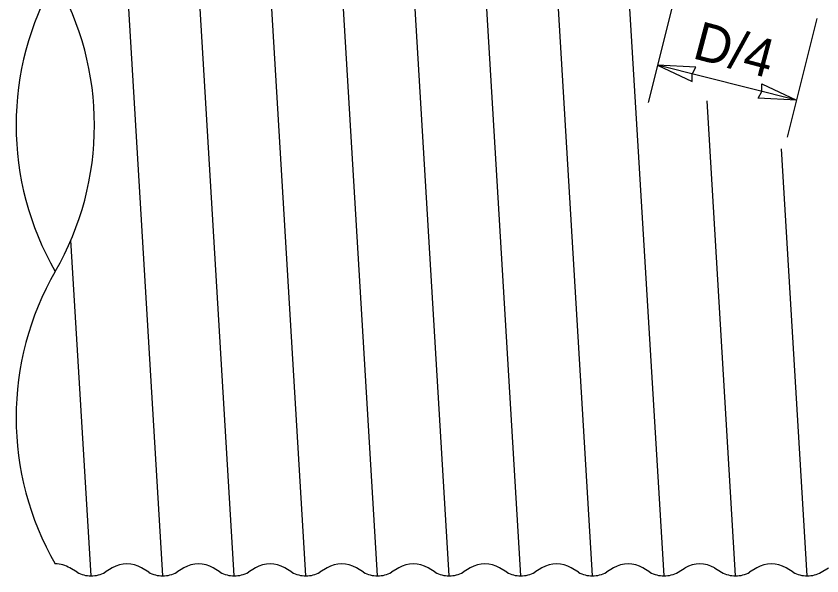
# Model space of a CAD drawing. Extents: x 99862 to 103151, y 100000 to 102076.
# Drawn here: x 100599.7 to 100937.3, y 101551.1 to 101785.5 of the extents above; entities that cross this region are included whole.
import ezdxf

# ---------------------------------------------------------------- set-up
doc = ezdxf.new("R2010")
doc.units = 0
for name, color, linetype in [('Level 1', 7, 'Continuous'), ('Level 15', 7, 'Continuous'), ('Level 20', 7, 'Continuous')]:
    doc.layers.add(name, color=color, linetype=linetype)

msp = doc.modelspace()

# ---------------------------------------------------------------- linework, layer by layer
at = {"layer": 'Level 1'}
for p, q in [((100661.12, 101551.13), (100646.12, 101801.13)), ((100691.12, 101551.13), (100676.12, 101801.13)), ((100721.12, 101551.13), (100706.12, 101801.13)), ((100751.12, 101551.13), (100736.12, 101801.13)), ((100781.12, 101551.13), (100766.12, 101801.13)), ((100811.12, 101551.13), (100796.12, 101801.13)), ((100841.12, 101551.13), (100826.12, 101801.13)), ((100871.12, 101551.13), (100856.12, 101801.13)), ((100901.12, 101551.13), (100889.19, 101750.04)), ((100931.12, 101551.13), (100920.39, 101729.9)), ((100631.12, 101551.13), (100622.68, 101691.75)), ((100625.25, 101552.66), (100622.26, 101554.44)), ((100622.26, 101554.44), (100622.26, 101554.44)), ((100639.98, 101554.44), (100637, 101552.66)), ((100655.25, 101552.66), (100652.26, 101554.44)), ((100669.98, 101554.44), (100667, 101552.66)), ((100685.25, 101552.66), (100682.26, 101554.44)), ((100699.98, 101554.44), (100697, 101552.66)), ((100715.25, 101552.66), (100712.26, 101554.44)), ((100729.98, 101554.44), (100727, 101552.66)), ((100745.25, 101552.66), (100742.26, 101554.44)), ((100759.98, 101554.44), (100757, 101552.66)), ((100775.25, 101552.66), (100772.26, 101554.44)), ((100789.98, 101554.44), (100787, 101552.66)), ((100805.25, 101552.66), (100802.26, 101554.44)), ((100819.98, 101554.44), (100817, 101552.66)), ((100835.25, 101552.66), (100832.26, 101554.44)), ((100849.98, 101554.44), (100847, 101552.66)), ((100865.25, 101552.66), (100862.26, 101554.44)), ((100877, 101552.66), (100879.98, 101554.44)), ((100892.26, 101554.44), (100895.25, 101552.66)), ((100909.98, 101554.44), (100907, 101552.66)), ((100925.25, 101552.66), (100922.26, 101554.44)), ((100937, 101552.66), (100939.98, 101554.44))]:
    msp.add_line(p, q, dxfattribs=at)
msp.add_lwpolyline([(100926.64, 101750.39), (100910.63, 101751.21), (100912.09, 101754.02), (100912.13, 101757.19)], close=True, dxfattribs=at)
for centre, radius, start, end in [((100722.21, 101739.88), 122.5, 150, 210), ((100510.03, 101739.88), 122.5, 330, 30), ((100722.21, 101617.38), 122.5, 150, 210), ((100616.12, 101544.13), 12, 59.2401, 90), ((100646.12, 101544.13), 12, 59.2401, 120.7599), ((100676.12, 101544.13), 12, 59.2401, 120.7599), ((100706.12, 101544.13), 12, 59.2401, 120.7599), ((100736.12, 101544.13), 12, 59.2401, 120.7599), ((100766.12, 101544.13), 12, 59.2401, 120.7599), ((100796.12, 101544.13), 12, 59.2401, 120.7599), ((100826.12, 101544.13), 12, 59.2401, 120.7599), ((100856.12, 101544.13), 12, 59.2401, 120.7599), ((100886.12, 101544.13), 12, 59.2401, 120.7599), ((100916.12, 101544.13), 12, 59.2401, 120.7599), ((100631.12, 101563.13), 12, 240.6871, 270), ((100631.12, 101563.13), 12, 270, 299.3129), ((100661.12, 101563.13), 12, 240.6871, 270), ((100661.12, 101563.13), 12, 270, 299.3129), ((100691.12, 101563.13), 12, 240.6871, 270), ((100691.12, 101563.13), 12, 270, 299.3129), ((100721.12, 101563.13), 12, 240.6871, 270), ((100721.12, 101563.13), 12, 270, 299.3129), ((100751.12, 101563.13), 12, 240.6871, 270), ((100751.12, 101563.13), 12, 270, 299.3129), ((100781.12, 101563.13), 12, 240.6871, 270), ((100781.12, 101563.13), 12, 270, 299.3129), ((100811.12, 101563.13), 12, 240.6871, 270), ((100811.12, 101563.13), 12, 270, 299.3129), ((100841.12, 101563.13), 12, 240.6871, 270), ((100841.12, 101563.13), 12, 270, 299.3129), ((100871.12, 101563.13), 12, 240.6871, 270), ((100871.12, 101563.13), 12, 270, 299.3129), ((100901.12, 101563.13), 12, 240.6871, 270), ((100901.12, 101563.13), 12, 270, 299.3129), ((100931.12, 101563.13), 12, 240.6871, 270), ((100931.12, 101563.13), 12, 270, 299.3129)]:
    msp.add_arc(centre, radius, start, end, dxfattribs=at)
at = {"layer": 'Level 15'}
for p, q in [((100876.95, 101799.04), (100864.55, 101749.42)), ((100935.16, 101784.48), (100922.76, 101734.87)), ((100926.64, 101750.39), (100868.43, 101764.94))]:
    msp.add_line(p, q, dxfattribs=at)
msp.add_lwpolyline([(100868.43, 101764.94), (100882.93, 101758.13), (100882.98, 101761.3), (100884.43, 101764.12)], close=True, dxfattribs=at)

# ---------------------------------------------------------------- texts
at = {"layer": 'Level 20'}
msp.add_text('D/4', height=16, rotation=345.2084, dxfattribs=at).set_placement((100882.52, 101768.05))

doc.saveas('drawing.dxf')
